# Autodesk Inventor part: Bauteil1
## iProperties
Created: 2005-05
Part Number: Bauteil1
Document SubType Name: Modeling
Designer: Target
Manufacturer: Standard
Standards Organization: Custom
Author: Target
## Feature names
1. Extrusion2
